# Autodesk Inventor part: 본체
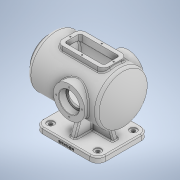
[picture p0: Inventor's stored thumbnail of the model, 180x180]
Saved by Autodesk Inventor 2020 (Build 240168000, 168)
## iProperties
Created: 2021-11
Part Number: 본체
Material: 일반
Document SubType Name: Modeling
Designer: USER
Density: 1 g/cm^3
Appearance: 기본값
Mass: 1311.31 g
Surface Area: 2404.13 cm^2
Volume: 1311.31 cm^3
Author: USER
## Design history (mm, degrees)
sketch "스케치1"
  geometry: L1 (0, 0)-(-160, 0); L2 (-160, 0)-(-160, -130); L3 (-160, -130)-(0, -130); L4 (0, -130)-(0, 0)
  constraints: 8 end point, 2 parallel, 1 horizontal, 1 perpendicular
  dimensions: "d0" = 160 distance of L3.end L2.end; "d1" = 130 distance of L2.end L1.end
extrude "돌출1" new body sketch "스케치1" distance "d2" = 14; taper "d3" = 0 deg
fillet "모깎기1" dims "d4" = 20
sketch "스케치2"
  geometry: A1 r 20 centre (140, 110) between (160, 110) and (140, 130) reference; A2 r 20 centre (140, 20) between (140, 0) and (160, 20) reference; A3 r 20 centre (20, 20) between (0, 20) and (20, 0) reference; A4 r 20 centre (20, 110) between (20, 130) and (0, 110) reference; 5 further points
  constraints: 4 coincident
hole "구멍1" sketch "스케치2" at (140, 110), (140, 20), (20, 20), (20, 110) diameter "d5" = 9; stored, may be unused: countersink angle "d9" = 90 deg, drill point angle "d11" = 118 deg; dims "d6" = 10, "d7" = 18, "d8" = 2, "d10" = 14
fillet "모깎기2" dims "d12" = 3
node "작업 평면1"
sketch "스케치3"
  geometry: L1 (0, 14)-(120, 14) reference; L2 (0, 0)-(-20, 0) reference; L3 (-50, 114)-(160, 114); L4 (-50, 146.5)-(-50, 161.5); L5 (-50, 161.5)-(-40, 161.5); L6 (-40, 161.5)-(-40, 179); L7 (-40, 179)-(135.993, 179); L8 (-50, 146.5)-(-25, 146.5); L9 (-25, 146.5)-(-25, 169); L10 (-25, 169)-(131.239, 169); A1 r 100 centre (60, 114) between (-40, 114) and (135.993, 179); A2 r 90 centre (60, 114) between (-30, 114) and (131.239, 169); 2 further points
  constraints: 16 end point, 5 perpendicular, 4 point on circle, 2 centre point, 2 horizontal, 2 point on line, 1 horizontal alignment, 1 vertical, 1 vertical alignment
  dimensions: "d16" = 210 distance of L3.start L3.end; "d18" = 114 vertical distance of L2.end L3.start; "d19" = 30 horizontal distance of L2.end L3.start; "d20" = 65 diameter of L8 L3; "d21" = 95 diameter of L5 L3; "d22" = 110 diameter of L10 L3; "d23" = 130 diameter of L7 L3; "d24" = 25 distance between parallel lines of L9 L4; "d25" = 10 distance between parallel lines of L4 L6; "d26" = 200 diameter of A1; "d27" = 210 dimension on A1 L4; "d28" = 10 radial gap between concentric circles of A1 A2
revolve "회전1" sketch "스케치3" stored, may be unused: angle "d29" = 90 deg
fillet "모깎기3" dims "d30" = 10
node "작업 평면2"
sketch "스케치4"
  geometry: L1 (-50, 66.5)-(-50, 161.5) reference; C1 r 40 at (77, 114); 2 further points
  constraints: 1 centre point, 1 horizontal alignment, 1 midpoint
  dimensions: "d32" = 80 diameter of C1; "d33" = 127 distance from line of L1 C1.centre
extrude "돌출2" join sketch "스케치4" stored distance "d34" = 14; taper "d35" = 0 deg
node "작업 평면3"
sketch "스케치5"
  geometry: C1 r 40 at (43, 114) reference; C2 r 40 at (43, 114); 1 further point
  constraints: 1 centre point, 1 coincident
  dimensions: "d37" = 80 diameter of C2
extrude "돌출3" join sketch "스케치5" stored distance "d38" = 14; taper "d39" = 0 deg
sketch "스케치6"
  geometry: C1 r 40 at (0, 0) reference; C2 r 21 at (0, 0); 1 further point
  constraints: 1 centre point, 1 coincident
  dimensions: "d40" = 42 diameter of C2
extrude "돌출4" cut sketch "스케치6" extent not by distance; stored distance "d41" = 0; taper "d42" = 0 deg
node "작업 평면4"
sketch "스케치7"
  geometry: L1 (20, -95)-(140, -95); L2 (140, -95)-(140, -35); L3 (140, -35)-(20, -35); L4 (20, -35)-(20, -95); L5 (-30, -112.5)-(-30, -17.5) reference; 3 further points
  constraints: 8 end point, 2 midpoint, 2 parallel, 1 horizontal, 1 horizontal alignment, 1 perpendicular
  dimensions: "d44" = 60 distance between parallel lines of L3 L1; "d45" = 120 distance of L2.end L3.end; "d46" = 50 distance between parallel lines of L5 L4
extrude "돌출5" join sketch "스케치7" stored distance "d47" = 14; taper "d48" = 0 deg
sketch "스케치8"
  geometry: L1 (30, 85)-(130, 85); L2 (130, 85)-(130, 45); L3 (130, 45)-(30, 45); L4 (30, 45)-(30, 85); L5 (20, 95)-(140, 95) reference; L6 (20, 35)-(20, 95) reference; L7 (140, 35)-(20, 35) reference; L8 (140, 95)-(140, 35) reference; 1 further point
  constraints: 8 end point, 2 parallel, 1 horizontal, 1 perpendicular
  dimensions: "d49" = 10 distance between parallel lines of L1 L5; "d50" = 10 distance between parallel lines of L6 L4; "d51" = 10 distance between parallel lines of L7 L3; "d52" = 10 distance between parallel lines of L8 L2
extrude "돌출6" cut sketch "스케치8" distance "d53" = 35.5; taper "d54" = 0 deg
fillet "모깎기4" dims "d55" = 15, "d162" = 5
fillet "모깎기5" dims "d56" = 3
sketch "스케치9"
  geometry: L1 (73, 90)-(87, 90); L2 (87, 90)-(87, 40); L3 (87, 40)-(73, 40); L4 (73, 40)-(73, 90); L5 (0, 110)-(0, 20) reference; L6 (140, 130)-(20, 130) reference; 5 further points
  constraints: 8 end point, 4 midpoint, 2 parallel, 1 horizontal, 1 horizontal alignment, 1 perpendicular, 1 vertical alignment
  dimensions: "d57" = 14 distance of L1.start L1.end; "d58" = 50 distance of L1.end L2.end
extrude "돌출7" join sketch "스케치9" stored distance "d59" = 35.5; taper "d60" = 0 deg
sketch "스케치10"
  geometry: L1 (53, 14)-(53, 54) reference; L2 (-17, 14)-(0, 14) reference; L3 (0, 14)-(16.327, 58.859); 1 further point
  constraints: 2 end point, 1 point on line
  dimensions: "d63" = 53 distance from line of L1 L3.start; "d64" = 110 deg angle of L2 L3
feature "리브1" sketch "스케치10" dims "d65" = 1, "d66" = 14, "d67" = 0, "d68" = 0, "d69" = 1, "d70" = 1
sketch "스케치11"
  geometry: L1 (111, 14)-(129, 14) reference; L2 (106.542, 50.975)-(120, 14); L3 (120, 14)-(137, 14) reference; L4 (67, 14)-(67, 54) reference; 1 further point
  constraints: 2 end point, 1 point on line
  dimensions: "d71" = 53 distance from line of L4 L2.end; "d72" = 110 deg angle of L3 L2
feature "리브2" sketch "스케치11" dims "d73" = 1, "d74" = 14, "d75" = 0, "d76" = 0, "d77" = 1, "d78" = 1
node "작업 평면5"
sketch "스케치12"
  geometry: L1 (-17, 14)-(0, 14) reference; L2 (-5, 14)-(12.196, 61.247); C1 r 55 at (45, 114) reference; 1 further point
  constraints: 2 end point, 1 point on line
  dimensions: "d80" = 50 horizontal distance of C1.centre L2.start; "d81" = 110 deg angle of L1 L2
feature "리브3" sketch "스케치12" dims "d82" = 1, "d83" = 14, "d84" = 0, "d85" = 0, "d86" = 1, "d87" = 1
sketch "스케치13"
  geometry: L1 (81, 14)-(99, 14) reference; L2 (95, 14)-(77.566, 61.899); L3 (90, 14)-(107, 14) reference; C1 r 32.5 at (45, 114) reference; 1 further point
  constraints: 2 end point, 1 point on line
  dimensions: "d88" = 50 horizontal distance of L2.start C1.centre; "d89" = 110 deg angle of L3 L2
feature "리브4" sketch "스케치13" dims "d90" = 1, "d91" = 14, "d92" = 0, "d93" = 0, "d94" = 1, "d95" = 1
fillet "모깎기6" dims "d96" = 3
fillet "모깎기7" dims "d97" = 3
chamfer "모따기1" distance "d98" = 1; stored, may be unused: second distance "d99" = 2, angle "d100" = 45 deg
fillet "모깎기8" dims "d101" = 3
sketch "스케치14"
  geometry: L1 (-30, 17.5)-(-30, 112.5) reference; L2 (137, 140)-(57, 140) reference; L3 (20, 50)-(20, 80) reference; L4 (140, 80)-(140, 50) reference; L5 (35, 95)-(125, 95) reference; 6 further points
  constraints: 2 horizontal alignment, 1 midpoint, 1 vertical alignment
  dimensions: "d102" = 50 distance of point (80, 40) point (80, 90); "d103" = 5 distance from line of L3 point (25, 65); "d104" = 5 distance from line of L4 point (135, 65); "d105" = 55 horizontal distance of point (25, 65) point (80, 90); "d106" = 5 distance from line of point (80, 90) L5
hole "구멍2" sketch "스케치14" at (80, 90), (80, 40), (135, 65), (25, 65) diameter "d107" = 3.242; stored, may be unused: countersink angle "d111" = 90 deg, drill point angle "d113" = 118 deg; dims "d108" = 9, "d109" = 18, "d110" = 2, "d112" = 11
sketch "스케치15"
  geometry: C1 r 22 at (0, 0) reference; C2 r 26 at (0, 0); 1 further point
  constraints: 1 centre point, 1 coincident
  dimensions: "d115" = 52 diameter of C2
extrude "돌출8" cut sketch "스케치15" distance "d116" = 18; taper "d117" = 0 deg
sketch "스케치16"
  geometry: C1 r 40 at (0, 0) reference; C2 r 26 at (0, 0); 1 further point
  constraints: 1 centre point, 1 coincident
  dimensions: "d118" = 52 diameter of C2
extrude "돌출9" cut sketch "스케치16" distance "d119" = 18; taper "d120" = 0 deg
sketch "스케치17"
  geometry: C1 r 21 at (0, 0) reference; 2 further points
  constraints: 1 vertical alignment
  dimensions: "d121" = 32.5 distance of C1.centre point (0, 32.5)
hole "구멍3" sketch "스케치17" at (0, 32.5) diameter "d122" = 3.242; stored, may be unused: countersink angle "d126" = 90 deg, drill point angle "d128" = 118 deg; dims "d123" = 11, "d124" = 4, "d125" = 2, "d127" = 13
sketch "스케치18"
  geometry: C1 r 40 at (0, 0) reference; 2 further points
  constraints: 1 vertical alignment
  dimensions: "d132" = 32.5 distance of C1.centre point (0, 32.5)
hole "구멍4" sketch "스케치18" at (0, 32.5) diameter "d133" = 3.242; stored, may be unused: countersink angle "d137" = 90 deg, drill point angle "d139" = 118 deg; dims "d134" = 11, "d135" = 4, "d136" = 2, "d138" = 13
sketch "스케치19"
  geometry: C1 r 47.5 at (0, 0) reference; 2 further points
  constraints: 1 vertical alignment
  dimensions: "d143" = 40 distance of C1.centre point (0, 40)
hole "구멍5" sketch "스케치19" at (0, 40) diameter "d144" = 3.242; stored, may be unused: countersink angle "d148" = 90 deg, drill point angle "d150" = 118 deg; dims "d145" = 11, "d146" = 4, "d147" = 2, "d149" = 13
chamfer "모따기2" distance "d154" = 1; stored, may be unused: second distance "d155" = 2, angle "d156" = 45 deg
fillet "모깎기9" dims "d157" = 0.3
fillet "모깎기10" dims "d158" = 3
sketch "스케치20"
  geometry: L1 (0, 0)-(120, 0) reference; L2 (120, 14)-(0, 14) reference; 3 further points
  constraints: 1 midpoint, 1 vertical alignment, 1 other
  dimensions: "d159" = 5 distance from line of L1 point (60, 5)
feature "엠보싱1" sketch "스케치20" dims "d160" = 0.5, "d161" = 0
node "솔리드1"
pattern_circular "원형 패턴1" dims angle "d130" = 360 deg
pattern_circular "원형 패턴2" dims angle "d141" = 360 deg
pattern_circular "원형 패턴3" dims angle "d152" = 360 deg
feature "A9D066F2-1C7D-4E18-AEED-F7BC21143FA4" dims "d5" = 9, "d6" = 10, "d7" = 18, "d8" = 2, "d9" = 90 deg, "d10" = 14, "d11" = 118 deg
other parameters: "d13" = -65, "d43" = -184
